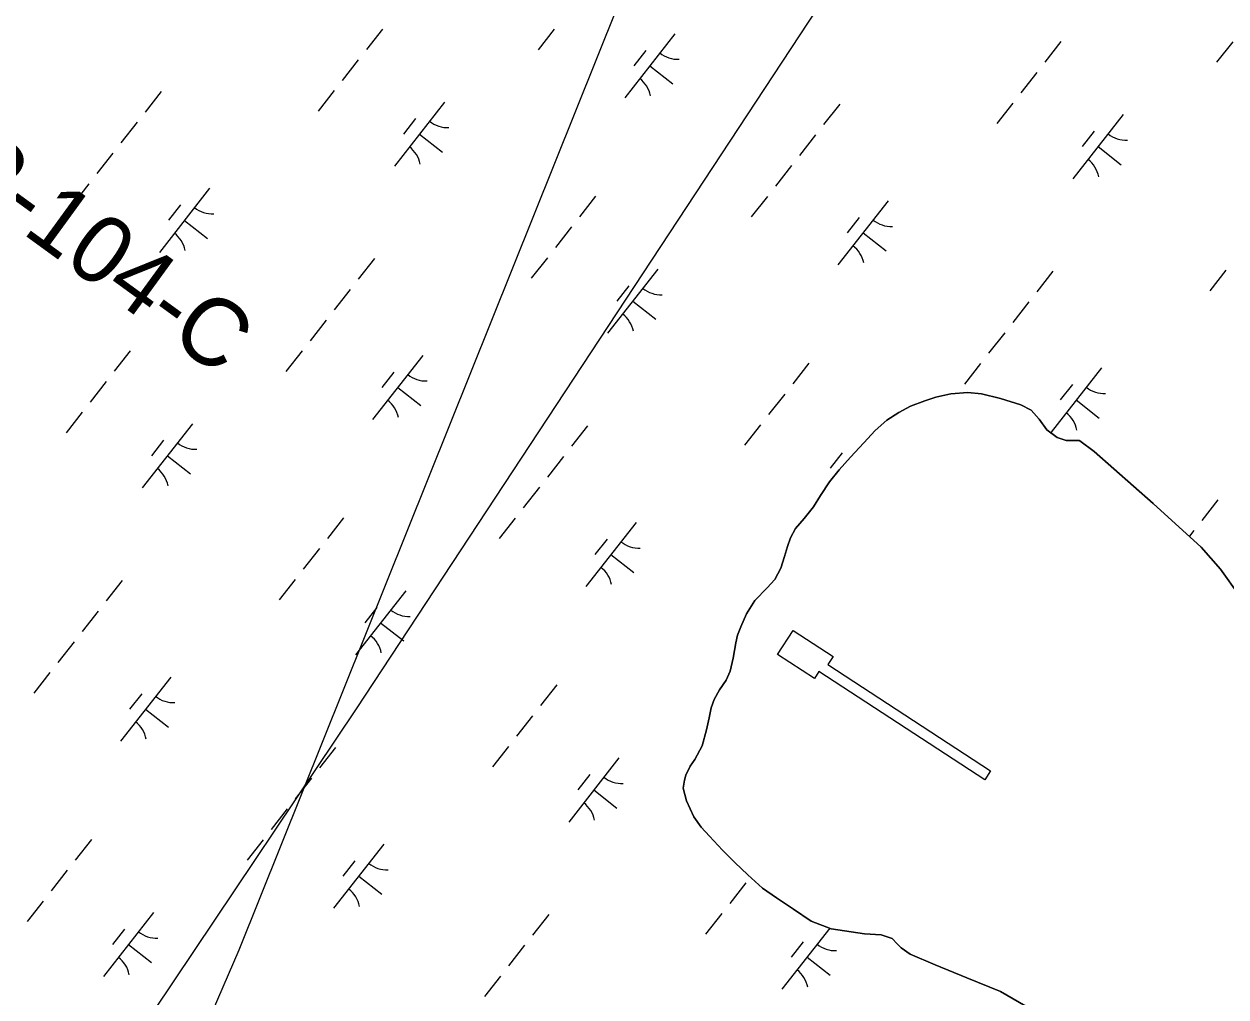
# Model space of a CAD drawing. Extents: x 3896831 to 3918110, y 171006 to 193349.
# Drawn here: x 3908805 to 3909543, y 178509 to 179106 of the extents above; entities that cross this region are included whole.
import ezdxf

# ---------------------------------------------------------------- set-up
doc = ezdxf.new("R2010")
doc.units = 0
for name, color, linetype in [('V-CHAN-DOCK', 7, 'Continuous'), ('V-GRID-MAJR', 7, 'Continuous'), ('V-RIVR-RANG-IDEN', 7, 'Continuous'), ('V-TOPO-SHOR', 7, 'Continuous'), ('V-UTIL-LINE', 7, 'Continuous'), ('V-WETL-SWMP', 7, 'Continuous')]:
    doc.layers.add(name, color=color, linetype=linetype)

msp = doc.modelspace()

# ---------------------------------------------------------------- linework, layer by layer
at = {"layer": 'V-CHAN-DOCK'}
msp.add_lwpolyline([(3909395.27, 178642.32), (3909293.49, 178708.7), (3909290.73, 178704.46), (3909268.09, 178719.23), (3909277.69, 178733.96), (3909302.23, 178717.96), (3909298.98, 178712.98), (3909398.87, 178647.84)], close=True, dxfattribs=at)
at = {"layer": 'V-GRID-MAJR'}
msp.add_spline([(3909752.76, 175802.03), (3909660.52, 181175.42), (3909556.5, 187235.56), (3909500.71, 190486.24)], degree=3, dxfattribs=at)
at = {"layer": 'V-TOPO-SHOR'}
for points in [[(3909428.28, 178498.65), (3909404.95, 178512.21), (3909384.32, 178520.65), (3909364.87, 178528.53), (3909349.4, 178535.13), (3909344.02, 178539.11), (3909341.53, 178541.57), (3909338.4, 178544.83), (3909331.64, 178547.11), (3909321.38, 178547.59), (3909301.04, 178550.82), (3909288.6, 178555.49), (3909277.81, 178562.79), (3909267.42, 178569.81), (3909258.87, 178575.73), (3909249.71, 178583.93), (3909241.73, 178591.56), (3909234.15, 178599.06), (3909226.33, 178607.63), (3909221.24, 178613.07), (3909216.57, 178619.44), (3909212.24, 178629.27), (3909210.14, 178637.19), (3909210.91, 178641.98), (3909211.77, 178645.02), (3909214.29, 178650.71), (3909217.31, 178654.78), (3909221.76, 178663.09), (3909224.5, 178672.91), (3909225.99, 178680.35), (3909227.32, 178686.46), (3909229.03, 178691.62), (3909232.36, 178697.56), (3909236.48, 178703.47), (3909239, 178709.02), (3909240.77, 178716.86), (3909242.44, 178726.43), (3909243.47, 178731.07), (3909245.58, 178736.23), (3909249.08, 178744.16), (3909254.19, 178752.33), (3909261.7, 178760.17), (3909266.34, 178765.28), (3909270.08, 178772.14), (3909272.37, 178779.43), (3909274.23, 178785.39), (3909275.95, 178790.83), (3909279.14, 178796.63), (3909284.47, 178802.65), (3909290.22, 178809.87), (3909294.5, 178816.71), (3909299.89, 178825.14), (3909305.78, 178832.49), (3909312.75, 178840.35), (3909320.94, 178849.24), (3909328.03, 178856.7), (3909335.24, 178863.08), (3909342.54, 178867.73), (3909349.69, 178871.58), (3909358.43, 178874.87), (3909365.29, 178877.26), (3909374.4, 178879.33), (3909384.96, 178880.05), (3909393.34, 178879.2), (3909404.89, 178876.43), (3909417.35, 178872.56), (3909423.82, 178869.22), (3909428.77, 178863.65), (3909433.3, 178857.15), (3909439.74, 178852.34)], [(3909439.74, 178852.34), (3909445.3, 178850.49), (3909453.44, 178850.58), (3909453.71, 178850.45), (3909462.5, 178843.86), (3909498.65, 178811.88), (3909528.24, 178785.1), (3909540.09, 178771.51), (3909551.62, 178755.13)]]:
    msp.add_lwpolyline(points, dxfattribs=at)
at = {"layer": 'V-UTIL-LINE'}
for points in [[(3905549.44, 173652.6), (3906763.35, 174938.42), (3906949.45, 175132.98), (3906970.6, 175166.82), (3907325.89, 175860.48), (3907748.86, 176681.03), (3908142.21, 177273.18), (3908679.38, 178097.96), (3908869.71, 178381.35), (3908937.39, 178537.85), (3909170.02, 179117.31), (3909533.77, 179633.33), (3910092.08, 180424.27), (3910333.17, 180766.87), (3910760.37, 181291.35), (3910921.09, 181523.98), (3911225.63, 181951.18), (3911822.01, 182788.65), (3911961.59, 182987.44), (3912147.69, 183114.33), (3912722.93, 183841.83), (3913090.91, 184307.09), (3913848.01, 185258.76), (3914364.03, 185910.13)], [(3913133.2, 183520.38), (3913116.28, 183516.15), (3912989.39, 183516.15), (3912744.07, 183393.49), (3911902.37, 182441.81), (3910866.11, 181249.05), (3910603.87, 180952.98), (3910214.74, 180504.64), (3910138.61, 180390.43), (3909757.94, 179819.43), (3909457.64, 179366.86), (3909009.29, 178685.89), (3908785.12, 178351.74), (3908150.67, 177400.07), (3907770.01, 176816.38), (3907693.87, 176706.41), (3907647.35, 176630.28), (3907300.51, 175936.61), (3907025.59, 175369.84), (3906945.22, 175204.88), (3906416.52, 174650.8), (3905507.14, 173682.21)]]:
    msp.add_lwpolyline(points, dxfattribs=at)
at = {"layer": 'V-WETL-SWMP'}
for p, q in [((3909025.43, 179103.21), (3909015.56, 179090.61)), ((3909130.89, 179103.07), (3909121.02, 179090.48)), ((3909205.02, 179100.34), (3909174.18, 179060.99)), ((3909442.07, 179095.51), (3909432.2, 179082.91)), ((3909547.53, 179095.38), (3909537.66, 179082.78)), ((3909187.23, 179090.14), (3909179.83, 179080.7)), ((3909010.62, 179084.32), (3909000.75, 179071.72)), ((3909189.6, 179080.66), (3909203.77, 179069.56)), ((3909427.26, 179076.62), (3909417.39, 179064.02)), ((3908889.58, 179064.84), (3908879.71, 179052.24)), ((3908995.82, 179065.43), (3908985.95, 179052.83)), ((3909063.63, 179058.39), (3909032.79, 179019.04)), ((3909306.22, 179057.14), (3909296.35, 179044.54)), ((3909412.46, 179057.73), (3909402.59, 179045.13)), ((3909045.84, 179048.2), (3909038.44, 179038.75)), ((3909480.28, 179050.69), (3909449.43, 179011.34)), ((3908874.77, 179045.95), (3908864.9, 179033.35)), ((3909048.21, 179038.71), (3909062.38, 179027.61)), ((3909291.42, 179038.25), (3909281.55, 179025.65)), ((3909462.48, 179040.5), (3909455.08, 179031.05)), ((3908859.97, 179027.06), (3908850.1, 179014.46)), ((3909464.85, 179031.01), (3909479.02, 179019.91)), ((3909276.61, 179019.36), (3909266.74, 179006.76)), ((3908845.16, 179008.17), (3908835.29, 178995.57)), ((3908919.3, 179005.43), (3908888.45, 178966.08)), ((3909156.34, 179000.6), (3909146.47, 178988)), ((3909261.81, 179000.47), (3909251.94, 178987.87)), ((3909335.94, 178997.73), (3909305.1, 178958.38)), ((3908901.51, 178995.24), (3908894.1, 178985.79)), ((3908903.88, 178985.75), (3908918.04, 178974.65)), ((3909318.15, 178987.54), (3909310.75, 178978.09)), ((3909141.54, 178981.71), (3909131.67, 178969.11)), ((3909320.52, 178978.05), (3909334.69, 178966.95)), ((3909020.5, 178962.23), (3909010.63, 178949.63)), ((3909126.73, 178962.82), (3909116.86, 178950.23)), ((3909194.55, 178955.78), (3909163.71, 178916.43)), ((3909437.14, 178954.53), (3909427.27, 178941.93)), ((3909543.38, 178955.12), (3909533.51, 178942.53)), ((3909176.76, 178945.59), (3909169.36, 178936.14)), ((3909005.69, 178943.34), (3908995.82, 178930.74)), ((3909179.13, 178936.11), (3909193.3, 178925)), ((3909422.34, 178935.64), (3909412.47, 178923.04)), ((3908990.89, 178924.45), (3908981.02, 178911.85)), ((3909407.53, 178916.75), (3909397.66, 178904.15)), ((3908870.62, 178905.69), (3908860.75, 178893.1)), ((3908976.08, 178905.56), (3908966.21, 178892.96)), ((3909050.22, 178902.82), (3909019.37, 178863.47)), ((3909287.26, 178897.99), (3909277.39, 178885.4)), ((3909392.73, 178897.86), (3909382.86, 178885.26)), ((3909466.86, 178895.12), (3909436.02, 178855.77)), ((3908855.82, 178886.8), (3908845.95, 178874.21)), ((3909032.42, 178892.63), (3909025.02, 178883.18)), ((3909034.8, 178883.15), (3909048.96, 178872.04)), ((3909272.46, 178879.1), (3909262.59, 178866.51)), ((3909374.4, 178879.33), (3909365.29, 178877.26)), ((3909384.96, 178880.05), (3909374.4, 178879.33)), ((3909393.35, 178879.2), (3909384.96, 178880.05)), ((3909404.89, 178876.42), (3909393.35, 178879.2)), ((3909449.07, 178884.93), (3909441.66, 178875.48)), ((3909349.69, 178871.58), (3909342.54, 178867.73)), ((3909358.43, 178874.87), (3909349.69, 178871.58)), ((3909365.29, 178877.26), (3909358.43, 178874.87)), ((3909417.35, 178872.56), (3909404.89, 178876.42)), ((3909423.82, 178869.22), (3909417.35, 178872.56)), ((3909451.44, 178875.45), (3909465.61, 178864.34)), ((3908841.01, 178867.91), (3908831.14, 178855.32)), ((3909342.54, 178867.73), (3909335.24, 178863.08)), ((3909428.77, 178863.65), (3909423.82, 178869.22)), ((3908908.83, 178860.87), (3908877.98, 178821.52)), ((3909151.42, 178859.62), (3909141.55, 178847.02)), ((3909257.65, 178860.21), (3909247.78, 178847.62)), ((3909328.03, 178856.7), (3909320.94, 178849.24)), ((3909335.24, 178863.08), (3909328.03, 178856.7)), ((3909433.3, 178857.15), (3909428.77, 178863.65)), ((3909439.74, 178852.34), (3909433.3, 178857.15)), ((3908891.03, 178850.68), (3908883.63, 178841.23)), ((3909320.94, 178849.24), (3909312.75, 178840.35)), ((3909445.3, 178850.49), (3909439.74, 178852.34)), ((3909453.44, 178850.59), (3909445.3, 178850.49)), ((3909453.71, 178850.45), (3909453.44, 178850.59)), ((3909462.51, 178843.86), (3909453.71, 178850.45)), ((3909307.68, 178842.98), (3909300.27, 178833.53)), ((3909498.65, 178811.88), (3909462.51, 178843.86)), ((3908893.4, 178841.2), (3908907.57, 178830.09)), ((3909136.61, 178840.73), (3909126.74, 178828.14)), ((3909312.75, 178840.35), (3909305.78, 178832.49)), ((3909305.78, 178832.49), (3909299.89, 178825.14)), ((3909121.81, 178821.84), (3909111.94, 178809.25)), ((3909299.89, 178825.14), (3909294.5, 178816.72)), ((3909294.5, 178816.72), (3909290.22, 178809.87)), ((3909538.45, 178814.14), (3909528.58, 178801.55)), ((3909290.22, 178809.87), (3909284.47, 178802.65)), ((3909528.24, 178785.1), (3909498.65, 178811.88)), ((3909001.54, 178803.08), (3908991.67, 178790.49)), ((3909107, 178802.95), (3909097.13, 178790.36)), ((3909181.14, 178800.21), (3909150.29, 178760.86)), ((3909284.47, 178802.65), (3909279.14, 178796.63)), ((3909163.34, 178790.02), (3909155.94, 178780.57)), ((3909275.95, 178790.83), (3909274.23, 178785.39)), ((3909279.14, 178796.63), (3909275.95, 178790.83)), ((3909523.64, 178795.25), (3909520.9, 178791.75)), ((3908986.73, 178784.19), (3908976.86, 178771.6)), ((3909274.23, 178785.39), (3909272.37, 178779.43)), ((3909540.09, 178771.51), (3909528.24, 178785.1)), ((3909165.71, 178780.54), (3909179.88, 178769.43)), ((3909272.37, 178779.43), (3909270.08, 178772.14)), ((3909270.08, 178772.14), (3909266.34, 178765.28)), ((3909551.62, 178755.13), (3909540.09, 178771.51)), ((3908865.69, 178764.71), (3908855.82, 178752.12)), ((3908971.93, 178765.3), (3908962.06, 178752.71)), ((3909266.34, 178765.28), (3909261.69, 178760.17)), ((3909039.74, 178758.26), (3909008.9, 178718.91)), ((3909261.69, 178760.17), (3909254.19, 178752.33)), ((3908850.89, 178745.82), (3908841.02, 178733.23)), ((3909021.95, 178748.07), (3909014.55, 178738.63)), ((3909254.19, 178752.33), (3909249.08, 178744.16)), ((3909024.32, 178738.59), (3909038.49, 178727.48)), ((3909249.08, 178744.16), (3909245.58, 178736.23)), ((3909243.47, 178731.08), (3909242.44, 178726.43)), ((3909245.58, 178736.23), (3909243.47, 178731.08)), ((3908836.08, 178726.93), (3908826.21, 178714.34)), ((3909242.44, 178726.43), (3909240.77, 178716.86)), ((3909240.77, 178716.86), (3909239, 178709.02)), ((3909239, 178709.02), (3909236.48, 178703.47)), ((3908821.28, 178708.04), (3908811.41, 178695.45)), ((3908895.41, 178705.31), (3908864.57, 178665.95)), ((3909236.48, 178703.47), (3909232.36, 178697.56)), ((3908877.62, 178695.11), (3908870.22, 178685.67)), ((3909132.46, 178700.47), (3909122.59, 178687.88)), ((3909232.36, 178697.56), (3909229.03, 178691.62)), ((3909229.03, 178691.62), (3909227.32, 178686.46)), ((3908879.99, 178685.63), (3908894.16, 178674.52)), ((3909117.65, 178681.58), (3909107.78, 178668.99)), ((3909225.99, 178680.35), (3909224.5, 178672.91)), ((3909227.32, 178686.46), (3909225.99, 178680.35)), ((3909224.5, 178672.91), (3909221.76, 178663.09)), ((3908996.61, 178662.1), (3908986.74, 178649.51)), ((3909102.85, 178662.69), (3909092.98, 178650.1)), ((3909221.76, 178663.09), (3909217.31, 178654.78)), ((3909170.66, 178655.66), (3909139.82, 178616.3)), ((3909214.29, 178650.71), (3909211.77, 178645.03)), ((3909217.31, 178654.78), (3909214.29, 178650.71)), ((3908981.81, 178643.21), (3908971.94, 178630.62)), ((3909152.87, 178645.46), (3909145.47, 178636.02)), ((3909211.77, 178645.03), (3909210.91, 178641.98)), ((3909155.24, 178635.98), (3909169.41, 178624.88)), ((3909210.91, 178641.98), (3909210.14, 178637.19)), ((3909210.14, 178637.19), (3909212.24, 178629.27)), ((3909212.24, 178629.27), (3909216.57, 178619.44)), ((3908967, 178624.32), (3908957.13, 178611.73)), ((3909216.57, 178619.44), (3909221.24, 178613.07)), ((3909221.24, 178613.07), (3909226.33, 178607.63)), ((3908846.73, 178605.56), (3908836.86, 178592.97)), ((3908952.2, 178605.43), (3908942.33, 178592.84)), ((3909226.33, 178607.63), (3909234.15, 178599.06)), ((3909026.33, 178602.7), (3908995.49, 178563.34)), ((3909234.15, 178599.06), (3909241.73, 178591.56)), ((3909008.54, 178592.5), (3909001.13, 178583.06)), ((3909241.73, 178591.56), (3909249.71, 178583.93)), ((3908831.93, 178586.67), (3908822.06, 178574.08)), ((3909249.71, 178583.93), (3909258.87, 178575.73)), ((3909010.91, 178583.02), (3909025.07, 178571.92)), ((3909248.57, 178578.97), (3909238.7, 178566.38)), ((3909258.87, 178575.73), (3909267.42, 178569.81)), ((3909267.42, 178569.81), (3909277.81, 178562.79)), ((3908817.12, 178567.78), (3908807.25, 178555.19)), ((3909277.81, 178562.79), (3909288.6, 178555.49)), ((3908884.94, 178560.75), (3908854.1, 178521.39)), ((3909127.53, 178559.49), (3909117.66, 178546.9)), ((3909233.77, 178560.08), (3909223.9, 178547.49)), ((3909288.6, 178555.49), (3909301.04, 178550.82)), ((3908867.15, 178550.55), (3908859.74, 178541.11)), ((3909300.11, 178551.17), (3909270.74, 178513.69)), ((3909301.04, 178550.82), (3909321.38, 178547.59)), ((3909321.38, 178547.59), (3909331.64, 178547.11)), ((3909331.64, 178547.11), (3909338.4, 178544.83)), ((3908869.52, 178541.07), (3908883.68, 178529.97)), ((3909112.72, 178540.6), (3909102.85, 178528.01)), ((3909283.79, 178542.85), (3909276.39, 178533.41)), ((3909338.4, 178544.83), (3909341.53, 178541.57)), ((3909341.53, 178541.57), (3909344.02, 178539.11)), ((3909344.02, 178539.11), (3909349.4, 178535.13)), ((3909286.16, 178533.37), (3909300.33, 178522.27)), ((3909349.4, 178535.13), (3909364.87, 178528.53)), ((3909364.87, 178528.53), (3909384.32, 178520.65)), ((3909097.92, 178521.71), (3909088.05, 178509.12)), ((3909384.32, 178520.65), (3909404.95, 178512.21)), ((3909404.95, 178512.21), (3909428.28, 178498.65))]:
    msp.add_line(p, q, dxfattribs=at)
for centre, start, end in [((3909206.83, 179102.26), 231.14028, 272.68394), ((3909172.75, 179058.78), 11.14028, 52.68394), ((3909065.44, 179060.31), 231.14028, 272.68394), ((3909482.08, 179052.61), 231.14028, 272.68394), ((3909031.36, 179016.83), 11.14028, 52.68394), ((3909448, 179009.13), 11.14028, 52.68394), ((3908921.1, 179007.35), 231.14028, 272.68394), ((3909337.75, 178999.65), 231.14028, 272.68394), ((3908887.02, 178963.87), 11.14028, 52.68394), ((3909303.67, 178956.17), 11.14028, 52.68394), ((3909196.35, 178957.7), 231.14028, 272.68394), ((3909162.28, 178914.22), 11.14028, 52.68394), ((3909052.02, 178904.74), 231.14028, 272.68394), ((3909468.66, 178897.04), 231.14028, 272.68394), ((3909017.94, 178861.26), 11.14028, 52.68394), ((3909434.59, 178853.56), 11.14028, 52.68394), ((3908910.63, 178862.79), 231.14028, 272.68394), ((3908876.55, 178819.31), 11.14028, 52.68394), ((3909182.94, 178802.13), 231.14028, 272.68394), ((3909148.86, 178758.65), 11.14028, 52.68394), ((3909041.55, 178760.18), 231.14028, 272.68394), ((3909007.47, 178716.7), 11.14028, 52.68394), ((3908897.21, 178707.22), 231.14028, 272.68394), ((3908863.14, 178663.74), 11.14028, 52.68394), ((3909172.47, 178657.57), 231.14028, 272.68394), ((3909138.39, 178614.09), 11.14028, 52.68394), ((3909028.13, 178604.61), 231.14028, 272.68394), ((3908994.06, 178561.13), 11.14028, 52.68394), ((3908886.74, 178562.66), 231.14028, 272.68394), ((3909303.39, 178554.96), 231.14028, 272.68394), ((3908852.67, 178519.18), 11.14028, 52.68394), ((3909269.31, 178511.48), 11.14028, 52.68394)]:
    msp.add_arc(centre, 17.62, start, end, dxfattribs=at)

# ---------------------------------------------------------------- texts
at = {"layer": 'V-RIVR-RANG-IDEN'}
msp.add_text('R-104-C', height=41.5, rotation=323.95282, dxfattribs=at).set_placement((3908756.12, 179012.72))

doc.saveas('drawing.dxf')
